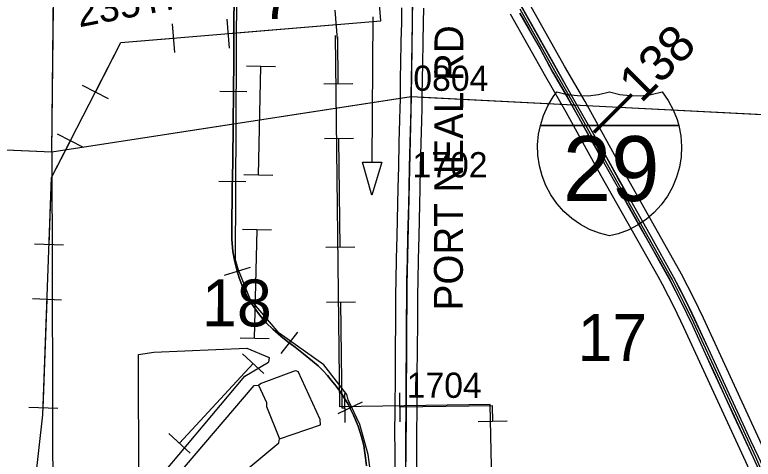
# Model space of a CAD drawing. Extents: x -157.2 to -99.3, y 12.2 to 46.2.
# Drawn here: x -146.931 to -144.882, y 26.222 to 27.455 of the extents above; entities that cross this region are included whole.
import ezdxf

# ---------------------------------------------------------------- set-up
doc = ezdxf.new("R2010")
doc.units = 0
for name, color, linetype in [('tdCoDirctArrow', 7, 'Continuous'), ('tdCoDivCarto', 7, 'Continuous'), ('tdCoHydroRiver', 7, 'Continuous'), ('tdCoInt', 7, 'Continuous'), ('tdCoIntCL', 7, 'Continuous'), ('tdCoIntRte', 7, 'Continuous'), ('tdCoPipe', 7, 'Continuous'), ('tdCoRRCL', 7, 'Continuous'), ('tdCoSecRdNmbr', 7, 'Continuous'), ('tdCoSecRdTxt', 7, 'Continuous'), ('tdCoSecRteBand', 7, 'Continuous'), ('tdCoSecRteCL', 7, 'Continuous'), ('tdCoSectLine', 7, 'Continuous'), ('tdCoSectLinePart', 7, 'Continuous'), ('tdCoSectNmbr', 7, 'Continuous'), ('tdCoShieldInt', 7, 'Continuous'), ('tdCoSurfAsphalt', 7, 'Continuous'), ('tdCoSurfConc', 7, 'Continuous'), ('tdStHwyIntRefPost1', 7, 'Continuous')]:
    doc.layers.add(name, color=color, linetype=linetype)

msp = doc.modelspace()

# ---------------------------------------------------------------- linework, layer by layer
at = {"layer": 'tdCoDirctArrow'}
msp.add_line((-145.9378, 27.4492), (-145.9409, 27.0466), dxfattribs=at)
msp.add_lwpolyline([(-145.9127, 27.0462), (-145.9408, 26.954), (-145.9666, 27.0462)], close=True, dxfattribs=at)
at = {"layer": 'tdCoDivCarto'}
for points in [[(-144.5268, 25.4922), (-144.5446, 25.5301), (-144.5853, 25.6187), (-144.6358, 25.7269), (-144.6935, 25.8534), (-144.7532, 25.9814), (-144.8097, 26.1025), (-144.8676, 26.2283), (-144.8886, 26.2729), (-144.9256, 26.3538), (-144.9544, 26.4157), (-144.9843, 26.4798), (-145.0062, 26.5284), (-145.0447, 26.61), (-145.0585, 26.6401), (-145.0814, 26.6865), (-145.1024, 26.7262), (-145.1682, 26.8443), (-145.2385, 26.9688), (-145.2565, 27.0007), (-145.3095, 27.0963), (-145.3835, 27.2263), (-145.4553, 27.3538), (-145.5303, 27.487)], [(-144.5268, 25.4922), (-144.5446, 25.5301), (-144.5853, 25.6187), (-144.6358, 25.7269), (-144.6935, 25.8534), (-144.7532, 25.9814), (-144.8097, 26.1025), (-144.8676, 26.2283), (-144.8886, 26.2729), (-144.9256, 26.3538), (-144.9544, 26.4157), (-144.9843, 26.4798), (-145.0062, 26.5284), (-145.0447, 26.61), (-145.0585, 26.6401), (-145.0814, 26.6865), (-145.1024, 26.7262), (-145.1682, 26.8443), (-145.2385, 26.9688), (-145.2565, 27.0007), (-145.3095, 27.0963), (-145.3835, 27.2263), (-145.4553, 27.3538), (-145.5303, 27.487)], [(-145.53, 27.4595), (-145.5063, 27.4171), (-145.4735, 27.3599), (-145.4385, 27.2958), (-145.3978, 27.2262), (-145.367, 27.1705), (-145.3352, 27.1135), (-145.3073, 27.0645), (-145.2938, 27.0395), (-145.2558, 26.9725), (-145.2257, 26.919), (-145.1961, 26.8664), (-145.1643, 26.8102), (-145.1389, 26.7648), (-145.113, 26.719), (-145.0829, 26.6598), (-145.0509, 26.5927), (-145.0153, 26.5148), (-144.9929, 26.4664), (-144.9616, 26.3984), (-144.9352, 26.3412), (-144.8822, 26.2267)], [(-145.53, 27.4595), (-145.5063, 27.4171), (-145.4735, 27.3599), (-145.4385, 27.2958), (-145.3978, 27.2262), (-145.367, 27.1705), (-145.3352, 27.1135), (-145.3073, 27.0645), (-145.2938, 27.0395), (-145.2558, 26.9725), (-145.2257, 26.919), (-145.1961, 26.8664), (-145.1643, 26.8102), (-145.1389, 26.7648), (-145.113, 26.719), (-145.0829, 26.6598), (-145.0509, 26.5927), (-145.0153, 26.5148), (-144.9929, 26.4664), (-144.9616, 26.3984), (-144.9352, 26.3412), (-144.8822, 26.2267)]]:
    msp.add_lwpolyline(points, dxfattribs=at)
at = {"layer": 'tdCoHydroRiver'}
for points in [[(-146.5874, 26.1528), (-146.5882, 26.5129), (-146.5453, 26.5194), (-146.2877, 26.5298), (-146.2254, 26.5041), (-146.2274, 26.4915)], [(-146.5548, 26.136), (-146.5447, 26.153), (-146.4758, 26.2344), (-146.2934, 26.4526), (-146.2274, 26.4915)], [(-146.2548, 26.4277), (-146.2499, 26.4322), (-146.1524, 26.4685), (-146.1446, 26.4651)], [(-146.1965, 26.2789), (-146.0831, 26.3177), (-146.0843, 26.332), (-146.1446, 26.4651)], [(-146.444, 26.1433), (-146.4944, 26.1466), (-146.4874, 26.1685), (-146.2674, 26.4265), (-146.2548, 26.4277)], [(-146.2548, 26.4277), (-146.2326, 26.3796), (-146.233, 26.3685), (-146.1965, 26.2789)], [(-146.444, 26.1433), (-146.3315, 26.157), (-146.1984, 26.2679), (-146.1965, 26.2789)]]:
    msp.add_lwpolyline(points, dxfattribs=at)
at = {"layer": 'tdCoInt'}
for points in [[(-144.2883, 25.2066), (-144.3658, 25.3), (-144.3919, 25.3324), (-144.4398, 25.3921), (-144.4543, 25.4114), (-144.4745, 25.4424), (-144.4946, 25.4783), (-144.508, 25.5047), (-144.5221, 25.5353), (-144.5684, 25.6351), (-144.8081, 26.1525), (-144.8216, 26.1806), (-144.8478, 26.2398), (-145.0204, 26.6132), (-145.0466, 26.6685), (-145.0811, 26.7352), (-145.0939, 26.7581), (-145.2516, 27.0373), (-145.349, 27.2141), (-145.4057, 27.3125), (-145.5032, 27.4853)], [(-144.3677, 25.2083), (-144.4123, 25.262), (-144.4387, 25.2948), (-144.4871, 25.3552), (-144.5035, 25.3769), (-144.5259, 25.4114), (-144.5475, 25.4501), (-144.562, 25.4785), (-144.5766, 25.5101), (-144.6229, 25.6099), (-144.8624, 26.1269), (-144.8761, 26.1556), (-144.9025, 26.2151), (-145.0747, 26.5877), (-145.1004, 26.6418), (-145.134, 26.7069), (-145.1462, 26.7289), (-145.304, 27.0081), (-145.4013, 27.1846), (-145.4579, 27.2828), (-145.5556, 27.456)]]:
    msp.add_lwpolyline(points, dxfattribs=at)
at = {"layer": 'tdCoIntCL'}
msp.add_lwpolyline([(-144.4633, 25.3719), (-144.4794, 25.3946), (-144.4899, 25.4097), (-144.4997, 25.4255), (-144.5094, 25.4426), (-144.5335, 25.4892), (-144.5393, 25.5015), (-144.5494, 25.5227), (-144.5679, 25.5624), (-144.8353, 26.1397), (-144.8488, 26.1681), (-144.8751, 26.2275), (-145.0475, 26.6004), (-145.0735, 26.6552), (-145.1076, 26.721), (-145.12, 26.7435), (-145.2778, 27.0227), (-145.3751, 27.1994), (-145.4318, 27.2976), (-145.5294, 27.4706)], dxfattribs=at)
at = {"layer": 'tdCoIntRte'}
for points in [[(-144.868, 26.2283), (-144.889, 26.2729), (-144.926, 26.3538), (-144.9548, 26.4157), (-144.9846, 26.4798), (-145.0066, 26.5284), (-145.0451, 26.61), (-145.0589, 26.6401), (-145.0818, 26.6865), (-145.1028, 26.7262), (-145.1686, 26.8443), (-145.2389, 26.9688), (-145.2569, 27.0007), (-145.3099, 27.0963), (-145.3839, 27.2263), (-145.4557, 27.3538), (-145.5306, 27.487)], [(-144.868, 26.2283), (-144.889, 26.2729), (-144.926, 26.3538), (-144.9548, 26.4157), (-144.9846, 26.4798), (-145.0066, 26.5284), (-145.0451, 26.61), (-145.0589, 26.6401), (-145.0818, 26.6865), (-145.1028, 26.7262), (-145.1686, 26.8443), (-145.2389, 26.9688), (-145.2569, 27.0007), (-145.3099, 27.0963), (-145.3839, 27.2263), (-145.4557, 27.3538), (-145.5306, 27.487)], [(-145.5304, 27.4595), (-145.5067, 27.4171), (-145.4739, 27.3599), (-145.4389, 27.2958), (-145.3982, 27.2262), (-145.3674, 27.1705), (-145.3356, 27.1135), (-145.3077, 27.0645), (-145.2941, 27.0395), (-145.2562, 26.9725), (-145.2261, 26.919), (-145.1965, 26.8664), (-145.1647, 26.8102), (-145.1393, 26.7648), (-145.1134, 26.719), (-145.0833, 26.6598), (-145.0512, 26.5927), (-145.0157, 26.5148), (-144.9933, 26.4664), (-144.962, 26.3984), (-144.9356, 26.3412), (-144.8826, 26.2267), (-144.8426, 26.1402)], [(-145.5304, 27.4595), (-145.5067, 27.4171), (-145.4739, 27.3599), (-145.4389, 27.2958), (-145.3982, 27.2262), (-145.3674, 27.1705), (-145.3356, 27.1135), (-145.3077, 27.0645), (-145.2941, 27.0395), (-145.2562, 26.9725), (-145.2261, 26.919), (-145.1965, 26.8664), (-145.1647, 26.8102), (-145.1393, 26.7648), (-145.1134, 26.719), (-145.0833, 26.6598), (-145.0512, 26.5927), (-145.0157, 26.5148), (-144.9933, 26.4664), (-144.962, 26.3984), (-144.9356, 26.3412), (-144.8826, 26.2267), (-144.8426, 26.1402)]]:
    msp.add_lwpolyline(points, dxfattribs=at)
at = {"layer": 'tdCoPipe'}
for p, q in [((-146.0358, 27.3871), (-146.0424, 27.4674)), ((-146.3358, 27.3621), (-146.3424, 27.4423)), ((-146.4873, 27.3496), (-146.4939, 27.4299)), ((-146.2081, 27.3098), (-146.2886, 27.3117)), ((-146.6716, 27.2218), (-146.7431, 27.2586)), ((-145.9933, 27.2631), (-146.0737, 27.2622)), ((-146.7411, 27.0866), (-146.8128, 27.1235)), ((-145.9915, 27.1111), (-146.0721, 27.1102)), ((-146.2151, 27.0088), (-146.2956, 27.0107)), ((-146.2187, 26.8569), (-146.2993, 26.8587)), ((-146.7959, 26.8154), (-146.8763, 26.8183)), ((-145.988, 26.8101), (-146.0685, 26.8091)), ((-146.8014, 26.6635), (-146.882, 26.6664)), ((-145.9862, 26.658), (-146.0668, 26.6571)), ((-146.2258, 26.5559), (-146.3062, 26.5578)), ((-146.2403, 26.4599), (-146.2995, 26.5146)), ((-146.0163, 26.4044), (-146.0151, 26.324)), ((-145.8642, 26.4066), (-145.8631, 26.3261)), ((-146.8123, 26.3626), (-146.8927, 26.3656)), ((-145.5649, 26.3275), (-145.6454, 26.3258)), ((-146.4447, 26.2389), (-146.5037, 26.2935))]:
    msp.add_line(p, q, dxfattribs=at)
for points in [[(-147.1212, 25.0341), (-146.8959, 25.966), (-146.8533, 26.3456), (-146.8295, 27.003), (-146.6367, 27.3776), (-145.9154, 27.4375), (-145.9326, 27.6455), (-145.5021, 27.6971), (-145.5064, 28.1719), (-145.3821, 28.2336), (-145.5249, 28.9444), (-144.8928, 29.2745), (-144.8343, 30.559), (-144.6513, 30.9418), (-144.6842, 32.0039)], [(-146.3391, 27.4023), (-146.0391, 27.4272)], [(-146.7074, 27.2403), (-146.6367, 27.3776), (-146.4906, 27.3897)], [(-143.1022, 23.5122), (-143.2095, 23.8428), (-143.9285, 23.9743), (-144.6565, 24.6805), (-145.5794, 24.8267), (-145.6123, 26.3736), (-146.0293, 26.3674), (-146.0413, 27.397)], [(-146.0336, 27.2627), (-146.0351, 27.3936)], [(-146.2554, 27.0098), (-146.2484, 27.3107)], [(-146.8362, 26.8169), (-146.8295, 27.003), (-146.7769, 27.1051)], [(-146.0283, 26.8096), (-146.0318, 27.1106)], [(-146.266, 26.5568), (-146.259, 26.8578)], [(-146.8526, 26.3641), (-146.8417, 26.6649)], [(-146.0157, 26.3641), (-146.0231, 26.364), (-146.0265, 26.6576)], [(-146.4742, 26.2662), (-146.2699, 26.4872)], [(-145.6052, 26.3267), (-145.6061, 26.3702), (-145.8636, 26.3664)]]:
    msp.add_lwpolyline(points, dxfattribs=at)
at = {"layer": 'tdCoRRCL'}
for p, q in [((-146.2872, 27.241), (-146.3621, 27.2421)), ((-146.29, 26.9909), (-146.365, 26.9922)), ((-146.2785, 26.7542), (-146.3501, 26.7318)), ((-146.1471, 26.5747), (-146.1927, 26.5152)), ((-145.9674, 26.3802), (-146.035, 26.3477))]:
    msp.add_line(p, q, dxfattribs=at)
for points in [[(-146.0104, 26.4013), (-146.074, 26.4839), (-146.1974, 26.5717), (-146.2781, 26.6659), (-146.3117, 26.7491), (-146.3188, 26.7746), (-146.3137, 27.9131), (-146.3213, 28.0192), (-146.3321, 28.0764), (-146.3225, 28.1282), (-146.3085, 28.3172), (-146.3124, 28.3458), (-146.297, 28.5269), (-146.2985, 28.8728), (-146.2968, 28.928), (-146.5997, 29.617)], [(-146.3226, 27.5145), (-146.3234, 27.4168), (-146.3234, 27.331), (-146.3247, 27.239), (-146.3252, 27.1536), (-146.3265, 27.0461), (-146.3278, 26.9709), (-146.3291, 26.8608), (-146.3291, 26.8319), (-146.326, 26.7981), (-146.321, 26.769), (-146.3155, 26.747), (-146.3087, 26.7252), (-146.3014, 26.7058), (-146.2914, 26.6833), (-146.2806, 26.6629), (-146.2683, 26.6445), (-146.2555, 26.6262), (-146.2442, 26.6123), (-146.2327, 26.5997), (-146.2156, 26.5824), (-146.1934, 26.5632), (-146.174, 26.548), (-146.1538, 26.5326), (-146.1299, 26.5142), (-146.1053, 26.4943), (-146.0893, 26.4807), (-146.0756, 26.467), (-146.0633, 26.4542), (-146.0534, 26.4413), (-146.04, 26.4251), (-146.0266, 26.4067), (-146.0049, 26.3716), (-146.0035, 26.3687), (-145.9915, 26.3438), (-145.9789, 26.3137), (-145.969, 26.2841), (-145.9632, 26.2605), (-145.9579, 26.2259), (-145.9551, 26.2038)], [(-145.9551, 26.2038), (-145.9579, 26.2259), (-145.9632, 26.2605), (-145.969, 26.2841), (-145.9789, 26.3137), (-145.9915, 26.3438), (-146.0035, 26.3687), (-146.0049, 26.3716), (-146.0266, 26.4067), (-146.04, 26.4251), (-146.0534, 26.4413), (-146.0633, 26.4542), (-146.0756, 26.467), (-146.0893, 26.4807), (-146.1053, 26.4943), (-146.1299, 26.5142), (-146.1538, 26.5326), (-146.174, 26.548), (-146.1934, 26.5632), (-146.2156, 26.5824), (-146.2327, 26.5997), (-146.2442, 26.6123), (-146.2555, 26.6262), (-146.2683, 26.6445), (-146.2806, 26.6629), (-146.2914, 26.6833), (-146.3014, 26.7058), (-146.3087, 26.7252), (-146.3155, 26.747), (-146.321, 26.769), (-146.326, 26.7981), (-146.3291, 26.8319), (-146.3291, 26.8608), (-146.3278, 26.9709), (-146.3265, 27.0461), (-146.3252, 27.1536), (-146.3247, 27.239), (-146.3234, 27.331), (-146.3234, 27.4168), (-146.3226, 27.5145)], [(-145.9421, 25.9727), (-145.9369, 26.0357), (-145.9408, 26.159), (-145.951, 26.2351), (-145.9736, 26.318), (-146.0061, 26.387), (-146.0104, 26.4013)]]:
    msp.add_lwpolyline(points, dxfattribs=at)
at = {"layer": 'tdCoSecRteBand'}
for points in [[(-145.8763, 26.2002), (-145.8763, 26.2539), (-145.8766, 26.2881), (-145.8766, 26.2884), (-145.8766, 26.2886), (-145.8758, 26.3659), (-145.8753, 26.4487), (-145.8753, 26.4487), (-145.8753, 26.4487), (-145.8745, 26.5326), (-145.8741, 26.5968), (-145.874, 26.5996), (-145.8738, 26.6794), (-145.8738, 26.6795), (-145.8738, 26.6797), (-145.8733, 26.7177), (-145.8733, 26.7178), (-145.8733, 26.718), (-145.8718, 26.7774), (-145.8706, 26.8414), (-145.8706, 26.8415), (-145.8706, 26.8416), (-145.8684, 26.9298), (-145.8674, 26.9744), (-145.8661, 27.0326), (-145.8661, 27.0326), (-145.8661, 27.0326), (-145.8647, 27.1007), (-145.8647, 27.1008), (-145.8647, 27.101), (-145.8627, 27.1623), (-145.8617, 27.197), (-145.8615, 27.2189), (-145.8615, 27.228), (-145.8615, 27.2281), (-145.8615, 27.2282), (-145.8607, 27.281), (-145.8607, 27.2811), (-145.8607, 27.2813), (-145.8597, 27.3174), (-145.859, 27.3805), (-145.859, 27.3807), (-145.859, 27.3809), (-145.8578, 27.4336), (-145.8575, 27.4736)], [(-145.7975, 27.473), (-145.7978, 27.433), (-145.7978, 27.4327), (-145.7978, 27.4325), (-145.799, 27.3796), (-145.7997, 27.3164), (-145.7997, 27.3162), (-145.7998, 27.316), (-145.8007, 27.2799), (-145.8015, 27.2274), (-145.8015, 27.2184), (-145.8017, 27.1962), (-145.8017, 27.1959), (-145.8017, 27.1956), (-145.8027, 27.1606), (-145.8027, 27.1605), (-145.8027, 27.1605), (-145.8047, 27.0992), (-145.8062, 27.0313), (-145.8074, 26.9731), (-145.8074, 26.9731), (-145.8074, 26.9731), (-145.8084, 26.9285), (-145.8084, 26.9284), (-145.8084, 26.9284), (-145.8106, 26.8402), (-145.8118, 26.7761), (-145.8118, 26.7761), (-145.8118, 26.776), (-145.8133, 26.7167), (-145.8138, 26.6791), (-145.814, 26.5993), (-145.814, 26.5992), (-145.814, 26.5992), (-145.8141, 26.5964), (-145.8145, 26.5321), (-145.8145, 26.5321), (-145.8145, 26.5321), (-145.8153, 26.4483), (-145.8158, 26.3654), (-145.8158, 26.3654), (-145.8158, 26.3653), (-145.8166, 26.2883), (-145.8163, 26.2542), (-145.8163, 26.2541), (-145.8163, 26.254), (-145.8163, 26.2002)]]:
    msp.add_lwpolyline(points, dxfattribs=at)
at = {"layer": 'tdCoSecRteCL'}
msp.add_lwpolyline([(-145.8463, 26.2002), (-145.8463, 26.254), (-145.8466, 26.2883), (-145.8458, 26.3656), (-145.8453, 26.4485), (-145.8445, 26.5323), (-145.8441, 26.5966), (-145.844, 26.5994), (-145.8438, 26.6793), (-145.8433, 26.7173), (-145.8418, 26.7767), (-145.8406, 26.8408), (-145.8384, 26.9291), (-145.8374, 26.9738), (-145.8362, 27.032), (-145.8347, 27.1), (-145.8327, 27.1614), (-145.8317, 27.1964), (-145.8315, 27.2187), (-145.8315, 27.2278), (-145.8307, 27.2805), (-145.8297, 27.3168), (-145.829, 27.3802), (-145.8278, 27.4332), (-145.8275, 27.4734)], dxfattribs=at)
at = {"layer": 'tdCoSectLine'}
for points in [[(-145.818, 28.2539), (-145.8318, 27.2278)], [(-146.8289, 27.0746), (-146.818, 28.045)], [(-146.8289, 27.0746), (-145.8318, 27.2278)], [(-145.8318, 27.2278), (-145.8438, 26.7044), (-145.8467, 26.2152)], [(-145.8318, 27.2278), (-144.8224, 27.1764)], [(-147.8099, 27.1167), (-146.8289, 27.0746)], [(-146.8289, 27.0746), (-146.8256, 26.0459)]]:
    msp.add_lwpolyline(points, dxfattribs=at)
at = {"layer": 'tdCoSectLinePart'}
for points in [[(-146.8289, 27.0746), (-146.8239, 27.5174)], [(-146.8289, 27.0746), (-145.8617, 27.2232)], [(-145.8016, 27.2262), (-144.8524, 27.1779)], [(-147.2711, 27.0936), (-146.8289, 27.0746)], [(-146.8289, 27.0746), (-146.8256, 26.0459)]]:
    msp.add_lwpolyline(points, dxfattribs=at)
at = {"layer": 'tdCoShieldInt'}
msp.add_line((-145.4697, 27.1475), (-145.0923, 27.1475), dxfattribs=at)
for points in [[(-145.2808, 26.8412), (-145.309, 26.8487), (-145.3362, 26.8594), (-145.3618, 26.8732), (-145.3857, 26.8899), (-145.4075, 26.9093), (-145.4269, 26.9311), (-145.4436, 26.955), (-145.4574, 26.9807), (-145.4681, 27.0078), (-145.4756, 27.036), (-145.4797, 27.0649), (-145.4805, 27.094), (-145.4778, 27.1231), (-145.4729, 27.1475), (-145.464, 27.1752), (-145.452, 27.2018), (-145.437, 27.2268), (-145.4268, 27.2407), (-145.3984, 27.2338), (-145.3695, 27.2303), (-145.3403, 27.2301), (-145.3113, 27.2334), (-145.2808, 27.2407), (-145.2525, 27.2338), (-145.2236, 27.2303), (-145.1944, 27.2301), (-145.1654, 27.2334), (-145.1349, 27.2407), (-145.1182, 27.2168), (-145.1044, 27.1911), (-145.0936, 27.164), (-145.0888, 27.1475), (-145.0833, 27.1188), (-145.0811, 27.0897), (-145.0824, 27.0606), (-145.087, 27.0318), (-145.095, 27.0038), (-145.1061, 26.9768), (-145.1204, 26.9514), (-145.1375, 26.9278), (-145.1572, 26.9063), (-145.1794, 26.8873), (-145.2035, 26.871), (-145.2295, 26.8576), (-145.2568, 26.8473)], [(-145.4729, 27.1475), (-145.464, 27.1752), (-145.452, 27.2018), (-145.437, 27.2268), (-145.4268, 27.2407), (-145.3984, 27.2338), (-145.3695, 27.2303), (-145.3403, 27.2301), (-145.3113, 27.2334), (-145.2808, 27.2407), (-145.2525, 27.2338), (-145.2236, 27.2303), (-145.1944, 27.2301), (-145.1654, 27.2334), (-145.1349, 27.2407), (-145.1182, 27.2168), (-145.1044, 27.1911), (-145.0936, 27.164), (-145.0888, 27.1475)], [(-145.2808, 26.8412), (-145.309, 26.8487), (-145.3362, 26.8594), (-145.3618, 26.8732), (-145.3857, 26.8899), (-145.4075, 26.9093), (-145.4269, 26.9311), (-145.4436, 26.955), (-145.4574, 26.9807), (-145.4681, 27.0078), (-145.4756, 27.036), (-145.4797, 27.0649), (-145.4805, 27.094), (-145.4778, 27.1231), (-145.4729, 27.1475), (-145.0888, 27.1475), (-145.0833, 27.1188), (-145.0811, 27.0897), (-145.0824, 27.0606), (-145.087, 27.0318), (-145.095, 27.0038), (-145.1061, 26.9768), (-145.1204, 26.9514), (-145.1375, 26.9278), (-145.1572, 26.9063), (-145.1794, 26.8873), (-145.2035, 26.871), (-145.2295, 26.8576), (-145.2568, 26.8473)]]:
    msp.add_lwpolyline(points, close=True, dxfattribs=at)
at = {"layer": 'tdCoSurfAsphalt'}
for points in [[(-145.8315, 27.2187), (-145.8315, 27.2278), (-145.8307, 27.2805), (-145.8297, 27.3168), (-145.829, 27.3802), (-145.8278, 27.4332), (-145.8275, 27.4734), (-145.826, 27.554), (-145.8251, 27.6147), (-145.8233, 27.7111), (-145.8229, 27.7341)], [(-145.8441, 26.5966), (-145.844, 26.5994), (-145.8438, 26.6793), (-145.8433, 26.7173), (-145.8418, 26.7767), (-145.8406, 26.8408), (-145.8384, 26.9291), (-145.8374, 26.9738), (-145.8362, 27.032), (-145.8347, 27.1), (-145.8327, 27.1614), (-145.8317, 27.1964), (-145.8315, 27.2187)]]:
    msp.add_lwpolyline(points, dxfattribs=at)
at = {"layer": 'tdCoSurfConc'}
msp.add_lwpolyline([(-145.8463, 26.2002), (-145.8463, 26.254), (-145.8466, 26.2883), (-145.8458, 26.3656), (-145.8453, 26.4485), (-145.8445, 26.5323), (-145.8441, 26.5966)], dxfattribs=at)

# ---------------------------------------------------------------- texts
at = {"layer": 'tdCoSecRdNmbr'}
for s, p in [('0804', (-145.8256, 27.2438)), ('1702', (-145.8278, 27.004)), ('1704', (-145.844, 26.3925))]:
    msp.add_text(s, height=0.07, rotation=359.8887, dxfattribs=at).set_placement(p)
at = {"layer": 'tdCoSecRdTxt'}
for s, rotation, p in [('235TH ST', 10.9319, (-146.7526, 27.4197)), ('PORT NEAL RD', 89.8851, (-145.6883, 26.6348))]:
    msp.add_text(s, height=0.08, rotation=rotation, dxfattribs=at).set_placement(p)
at = {"layer": 'tdCoSectNmbr'}
for s, rotation, p in [('7', 359.8882, (-146.2491, 27.4432)), ('18', 359.8882, (-146.4118, 26.5907)), ('17', 359.889, (-145.3701, 26.4947))]:
    msp.add_text(s, height=0.13, rotation=rotation, dxfattribs=at).set_placement(p)
at = {"layer": 'tdCoShieldInt'}
msp.add_text('29', height=0.18, dxfattribs=at).set_placement((-145.4103, 26.9381))
at = {"layer": 'tdStHwyIntRefPost1'}
msp.add_text('‒‒138', height=0.1, rotation=45, dxfattribs=at).set_placement((-145.2982, 27.1025))

doc.saveas('drawing.dxf')
